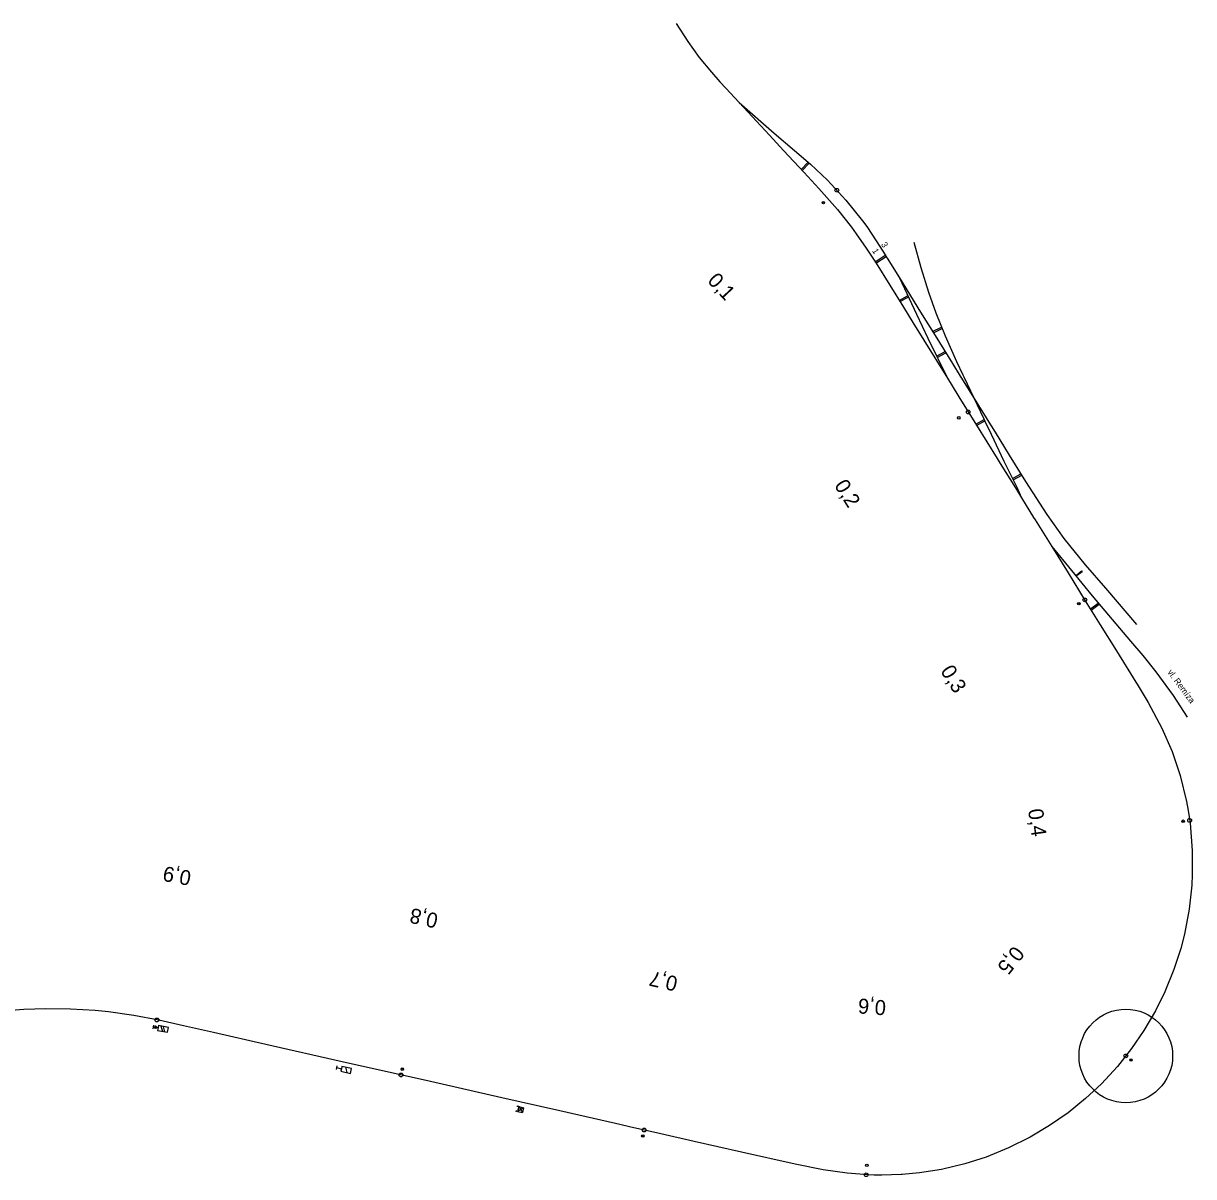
# Model space of a CAD drawing. Extents: x -738519 to -733269, y -1123734 to -1116309.
# Drawn here: x -734922.5 to -734453.9, y -1120225.8 to -1119763.8 of the extents above; entities that cross this region are included whole.
import ezdxf

# ---------------------------------------------------------------- set-up
doc = ezdxf.new("R2010")
doc.units = 0
doc.layers.add('Vrstva 1', color=7, linetype='Continuous')
doc.layers.add('Vrstva 7', color=7, linetype='Continuous')

msp = doc.modelspace()

# ---------------------------------------------------------------- linework, layer by layer
at = {"layer": 'Vrstva 1'}
for p, q in [((-734564.81, -1119880.31), (-734560.35, -1119889.86)), ((-734564.81, -1119880.31), (-734560.35, -1119889.86)), ((-734560.35, -1119889.86), (-734552.51, -1119905.98)), ((-734560.35, -1119889.86), (-734552.51, -1119905.98)), ((-734561.94, -1119890.77), (-734552.51, -1119905.98)), ((-734561.94, -1119890.77), (-734552.51, -1119905.98)), ((-734534.97, -1119928.42), (-734529.82, -1119939.22)), ((-734534.97, -1119928.42), (-734529.82, -1119939.22))]:
    msp.add_line(p, q, dxfattribs=at)
for points in [[(-734661.15, -1119763.83), (-734656.4, -1119771.12), (-734651.88, -1119777.47), (-734646.99, -1119783.39), (-734643.65, -1119787.17)], [(-734661.15, -1119763.83), (-734656.4, -1119771.12), (-734651.88, -1119777.47), (-734646.99, -1119783.39), (-734643.65, -1119787.17)], [(-734643.65, -1119787.17), (-734641.23, -1119789.79), (-734635.88, -1119795.55), (-734623.72, -1119808.66)], [(-734643.65, -1119787.17), (-734641.23, -1119789.79), (-734635.88, -1119795.55), (-734621.84, -1119807.82)], [(-734643.65, -1119787.17), (-734641.23, -1119789.79), (-734635.88, -1119795.55), (-734623.72, -1119808.66)], [(-734643.65, -1119787.17), (-734641.23, -1119789.79), (-734635.88, -1119795.55), (-734621.84, -1119807.82)], [(-734623.72, -1119808.66), (-734618.07, -1119814.79), (-734609.83, -1119823.62), (-734603.94, -1119829.94), (-734596.49, -1119838.41), (-734590.93, -1119845.44), (-734588.98, -1119848.11), (-734585, -1119853.83), (-734581.07, -1119859.88), (-734575.59, -1119868.67), (-734570.12, -1119877.53), (-734566.34, -1119883.67), (-734561.94, -1119890.77)], [(-734623.72, -1119808.66), (-734618.07, -1119814.79), (-734609.83, -1119823.62), (-734603.94, -1119829.94), (-734596.49, -1119838.41), (-734590.93, -1119845.44), (-734588.98, -1119848.11), (-734585, -1119853.83), (-734581.07, -1119859.88), (-734575.59, -1119868.67), (-734570.12, -1119877.53), (-734566.34, -1119883.67), (-734561.94, -1119890.77)], [(-734621.84, -1119807.82), (-734613.76, -1119814.7), (-734607.32, -1119820.27), (-734600.52, -1119826.61), (-734593.11, -1119834.58), (-734586.45, -1119842.91), (-734584.75, -1119845.25), (-734581.04, -1119850.86), (-734577.18, -1119856.99)], [(-734621.84, -1119807.82), (-734613.76, -1119814.7), (-734607.32, -1119820.27), (-734600.52, -1119826.61), (-734593.11, -1119834.58), (-734586.45, -1119842.91), (-734584.75, -1119845.25), (-734581.04, -1119850.86), (-734577.18, -1119856.99)], [(-734565.97, -1119851.41), (-734563.19, -1119861.58), (-734560.11, -1119871.47), (-734557.15, -1119879.72), (-734553.44, -1119889.01), (-734548.82, -1119899.31)], [(-734565.97, -1119851.41), (-734563.19, -1119861.58), (-734560.11, -1119871.47), (-734557.15, -1119879.72), (-734553.44, -1119889.01), (-734548.82, -1119899.31)], [(-734577.18, -1119856.99), (-734576.62, -1119857.91), (-734571.73, -1119865.79), (-734563.24, -1119879.48)], [(-734577.18, -1119856.99), (-734576.62, -1119857.91), (-734571.73, -1119865.79), (-734564.81, -1119880.31)], [(-734577.18, -1119856.99), (-734576.62, -1119857.91), (-734571.73, -1119865.79), (-734563.24, -1119879.48)], [(-734577.18, -1119856.99), (-734576.62, -1119857.91), (-734571.73, -1119865.79), (-734564.81, -1119880.31)], [(-734563.24, -1119879.48), (-734557.4, -1119888.87), (-734550.43, -1119900.11)], [(-734563.24, -1119879.48), (-734557.4, -1119888.87), (-734550.43, -1119900.11)], [(-734550.43, -1119900.11), (-734547.31, -1119905.14), (-734546.82, -1119905.94), (-734536.98, -1119921.77), (-734536.51, -1119922.56), (-734533.4, -1119927.58)], [(-734550.43, -1119900.11), (-734547.31, -1119905.14), (-734546.82, -1119905.94), (-734536.98, -1119921.77), (-734536.51, -1119922.56), (-734533.4, -1119927.58)], [(-734548.82, -1119899.31), (-734546.31, -1119904.61), (-734545.9, -1119905.46), (-734537.89, -1119922.29), (-734537.48, -1119923.12), (-734534.97, -1119928.42)], [(-734548.82, -1119899.31), (-734546.31, -1119904.61), (-734545.9, -1119905.46), (-734537.89, -1119922.29), (-734537.48, -1119923.12), (-734534.97, -1119928.42)], [(-734552.51, -1119905.98), (-734548.35, -1119912.69), (-734547.91, -1119913.38)], [(-734552.51, -1119905.98), (-734548.35, -1119912.69), (-734547.91, -1119913.38)], [(-734547.91, -1119913.38), (-734540.83, -1119924.83), (-734532.61, -1119938.09), (-734531.36, -1119940.09)], [(-734547.91, -1119913.38), (-734540.83, -1119924.83), (-734532.61, -1119938.09), (-734531.36, -1119940.09)], [(-734533.4, -1119927.58), (-734527.75, -1119936.72), (-734521.2, -1119947.31), (-734512.7, -1119960.57), (-734505.79, -1119970.12), (-734497.3, -1119980.65), (-734489.15, -1119990.09), (-734476.71, -1120004.56)], [(-734533.4, -1119927.58), (-734527.75, -1119936.72), (-734521.2, -1119947.31), (-734512.7, -1119960.57), (-734505.79, -1119970.12), (-734497.3, -1119980.65), (-734489.15, -1119990.09), (-734476.71, -1120004.56)], [(-734531.36, -1119940.09), (-734525.27, -1119949.91), (-734522.85, -1119953.82), (-734517.96, -1119961.71), (-734517.34, -1119962.72)], [(-734531.36, -1119940.09), (-734525.27, -1119949.91), (-734522.85, -1119953.82), (-734517.96, -1119961.71), (-734517.34, -1119962.72)], [(-734529.82, -1119939.22), (-734524.74, -1119949.62), (-734522.85, -1119953.82), (-734517.96, -1119961.71), (-734517.34, -1119962.72)], [(-734529.82, -1119939.22), (-734524.74, -1119949.62), (-734522.85, -1119953.82), (-734517.96, -1119961.71), (-734517.34, -1119962.72)], [(-734517.34, -1119962.72), (-734516.7, -1119963.74), (-734510.69, -1119973.42), (-734504.18, -1119983.89)], [(-734517.34, -1119962.72), (-734516.7, -1119963.74), (-734510.69, -1119973.42), (-734502.85, -1119982.93)], [(-734517.34, -1119962.72), (-734516.7, -1119963.74), (-734510.69, -1119973.42), (-734504.18, -1119983.89)], [(-734517.34, -1119962.72), (-734516.7, -1119963.74), (-734510.69, -1119973.42), (-734502.85, -1119982.93)], [(-734504.18, -1119983.89), (-734497.25, -1119995.08), (-734491.25, -1120004.74), (-734484.76, -1120015.19), (-734480.86, -1120021.45), (-734480.18, -1120022.55), (-734476.99, -1120027.68), (-734476.46, -1120028.54), (-734472.03, -1120035.88), (-734466.54, -1120046.18), (-734462.52, -1120055.45), (-734459.28, -1120065.13), (-734456.73, -1120075.49), (-734456.03, -1120079.17), (-734455.32, -1120084.21), (-734454.4, -1120095.11), (-734454.44, -1120105.99), (-734454.54, -1120107.84), (-734454.6, -1120109.09), (-734455.62, -1120118.65), (-734457.52, -1120128.68), (-734458.98, -1120134.34), (-734461.74, -1120142.87), (-734465.37, -1120151.8), (-734469.15, -1120159.42), (-734473.78, -1120167.32), (-734478.71, -1120174.52), (-734484.35, -1120181.61), (-734490.79, -1120188.56), (-734497.21, -1120194.54), (-734504.15, -1120200.17), (-734511.58, -1120205.34), (-734519.33, -1120209.98), (-734527.98, -1120214.28), (-734537.01, -1120217.94), (-734545.52, -1120220.65), (-734554.88, -1120222.87), (-734563.63, -1120224.26), (-734570.58, -1120224.9), (-734571.05, -1120224.92), (-734578.72, -1120225.21), (-734581.85, -1120225.14), (-734584.23, -1120225.09), (-734592.62, -1120224.46), (-734602.24, -1120223.05), (-734613.42, -1120220.79)], [(-734504.18, -1119983.89), (-734497.25, -1119995.08), (-734491.25, -1120004.74), (-734484.76, -1120015.19), (-734480.86, -1120021.45), (-734480.18, -1120022.55), (-734476.99, -1120027.68), (-734476.46, -1120028.54), (-734472.03, -1120035.88), (-734466.54, -1120046.18), (-734462.52, -1120055.45), (-734459.28, -1120065.13), (-734456.73, -1120075.49), (-734456.03, -1120079.17), (-734455.32, -1120084.21), (-734454.4, -1120095.11), (-734454.44, -1120105.99), (-734454.54, -1120107.84), (-734454.6, -1120109.09), (-734455.62, -1120118.65), (-734457.52, -1120128.68), (-734458.98, -1120134.34), (-734461.74, -1120142.87), (-734465.37, -1120151.8), (-734469.15, -1120159.42), (-734473.78, -1120167.32), (-734478.71, -1120174.52), (-734484.35, -1120181.61), (-734490.79, -1120188.56), (-734497.21, -1120194.54), (-734504.15, -1120200.17), (-734511.58, -1120205.34), (-734519.33, -1120209.98), (-734527.98, -1120214.28), (-734537.01, -1120217.94), (-734545.52, -1120220.65), (-734554.88, -1120222.87), (-734563.63, -1120224.26), (-734570.58, -1120224.9), (-734571.05, -1120224.92), (-734578.72, -1120225.21), (-734581.85, -1120225.14), (-734584.23, -1120225.09), (-734592.62, -1120224.46), (-734602.24, -1120223.05), (-734613.42, -1120220.79)], [(-734502.85, -1119982.93), (-734494.46, -1119993.2), (-734489.38, -1119999.18), (-734479.09, -1120011.24), (-734474.27, -1120017.09), (-734469.03, -1120023.64), (-734462.03, -1120033.09), (-734456.42, -1120041.8)], [(-734502.85, -1119982.93), (-734494.46, -1119993.2), (-734489.38, -1119999.18), (-734479.09, -1120011.24), (-734474.27, -1120017.09), (-734469.03, -1120023.64), (-734462.03, -1120033.09), (-734456.42, -1120041.8)], [(-734858.48, -1120165.34), (-734868.3, -1120163.18), (-734878.26, -1120161.29), (-734888.48, -1120159.82), (-734893.81, -1120159.29), (-734903.72, -1120158.67), (-734913.62, -1120158.56), (-734922.39, -1120158.89), (-734927.49, -1120159.26), (-734938.14, -1120160.47), (-734948.63, -1120162.22), (-734955.93, -1120163.8), (-734961.26, -1120165.13), (-734970.23, -1120167.73), (-734979.17, -1120170.78), (-734984.57, -1120172.85), (-734992.91, -1120176.44), (-734998.02, -1120178.89), (-735005.2, -1120182.65), (-735013.61, -1120187.35), (-735022.2, -1120192.38), (-735037.65, -1120201.44), (-735048.63, -1120207.9)], [(-734858.48, -1120165.34), (-734868.3, -1120163.18), (-734878.26, -1120161.29), (-734888.48, -1120159.82), (-734893.81, -1120159.29), (-734903.72, -1120158.67), (-734913.62, -1120158.56), (-734922.39, -1120158.89), (-734927.49, -1120159.26), (-734938.14, -1120160.47), (-734948.63, -1120162.22), (-734955.93, -1120163.8), (-734961.26, -1120165.13), (-734970.23, -1120167.73), (-734979.17, -1120170.78), (-734984.57, -1120172.85), (-734992.91, -1120176.44), (-734998.02, -1120178.89), (-735005.2, -1120182.65), (-735013.61, -1120187.35), (-735022.2, -1120192.38), (-735037.65, -1120201.44), (-735048.63, -1120207.9)], [(-734613.42, -1120220.79), (-734634.89, -1120215.96), (-734653.9, -1120211.66), (-734667.21, -1120208.65), (-734679.78, -1120205.8), (-734683.65, -1120204.92), (-734685.4, -1120204.52), (-734700.12, -1120201.2), (-734707.73, -1120199.48), (-734730.99, -1120194.2), (-734759.47, -1120187.75), (-734794.9, -1120179.75), (-734825.42, -1120172.84), (-734846.47, -1120168.09), (-734858.48, -1120165.34)], [(-734613.42, -1120220.79), (-734634.89, -1120215.96), (-734653.9, -1120211.66), (-734667.21, -1120208.65), (-734679.78, -1120205.8), (-734683.65, -1120204.92), (-734685.4, -1120204.52), (-734700.12, -1120201.2), (-734707.73, -1120199.48), (-734730.99, -1120194.2), (-734759.47, -1120187.75), (-734794.9, -1120179.75), (-734825.42, -1120172.84), (-734846.47, -1120168.09), (-734858.48, -1120165.34)]]:
    msp.add_lwpolyline(points, dxfattribs=at)
at = {"layer": 'Vrstva 7'}
for p, q in [((-734611.07, -1119822.29), (-734608.3, -1119819.42)), ((-734611.07, -1119822.29), (-734608.3, -1119819.42)), ((-734610.66, -1119822.73), (-734607.85, -1119819.81)), ((-734610.66, -1119822.73), (-734607.85, -1119819.81)), ((-734602.18, -1119835.62), (-734602.11, -1119835.7)), ((-734602.18, -1119835.62), (-734602.11, -1119835.7)), ((-734581.42, -1119859.33), (-734577.35, -1119856.73)), ((-734581.42, -1119859.33), (-734577.35, -1119856.73)), ((-734581.09, -1119859.84), (-734577.03, -1119857.24)), ((-734581.09, -1119859.84), (-734577.03, -1119857.24)), ((-734571.82, -1119874.78), (-734568.43, -1119872.91)), ((-734571.82, -1119874.78), (-734568.43, -1119872.91)), ((-734571.5, -1119875.29), (-734568.17, -1119873.45)), ((-734571.5, -1119875.29), (-734568.17, -1119873.45)), ((-734558.41, -1119887.26), (-734554.85, -1119885.47)), ((-734558.41, -1119887.26), (-734554.85, -1119885.47)), ((-734558.09, -1119887.77), (-734554.63, -1119886.03)), ((-734558.09, -1119887.77), (-734554.63, -1119886.03)), ((-734556.82, -1119897.12), (-734553.44, -1119895.25)), ((-734556.82, -1119897.12), (-734553.44, -1119895.25)), ((-734556.56, -1119897.66), (-734553.12, -1119895.76)), ((-734556.56, -1119897.66), (-734553.12, -1119895.76)), ((-734547.95, -1119921.8), (-734547.9, -1119921.88)), ((-734547.95, -1119921.8), (-734547.9, -1119921.88)), ((-734541.14, -1119924.33), (-734537.79, -1119922.49)), ((-734541.14, -1119924.33), (-734537.79, -1119922.49)), ((-734540.82, -1119924.84), (-734537.53, -1119923.03)), ((-734540.82, -1119924.84), (-734537.53, -1119923.03)), ((-734526.43, -1119946.16), (-734523.06, -1119944.3)), ((-734526.43, -1119946.16), (-734523.06, -1119944.3)), ((-734526.17, -1119946.7), (-734522.74, -1119944.81)), ((-734526.17, -1119946.7), (-734522.74, -1119944.81)), ((-734500.71, -1119984.73), (-734498.52, -1119983.46)), ((-734500.71, -1119984.73), (-734498.52, -1119983.46)), ((-734499.87, -1119996.2), (-734499.8, -1119996.28)), ((-734499.87, -1119996.2), (-734499.8, -1119996.28)), ((-734495.23, -1119998.34), (-734492.06, -1119996.03)), ((-734495.23, -1119998.34), (-734492.06, -1119996.03)), ((-734494.91, -1119998.85), (-734491.67, -1119996.49)), ((-734494.91, -1119998.85), (-734491.67, -1119996.49)), ((-734458.07, -1120083.38), (-734458.05, -1120083.48)), ((-734458.07, -1120083.38), (-734458.05, -1120083.48)), ((-734870.44, -1120165.12), (-734870.72, -1120166.6)), ((-734870.44, -1120165.12), (-734870.72, -1120166.6)), ((-734869.56, -1120165.95), (-734869.65, -1120165.93)), ((-734869.56, -1120165.95), (-734869.65, -1120165.93)), ((-734867.45, -1120165.44), (-734866.84, -1120167.59)), ((-734867.45, -1120165.44), (-734866.84, -1120167.59)), ((-734865.86, -1120167.78), (-734866.47, -1120165.63)), ((-734865.86, -1120167.78), (-734866.47, -1120165.63)), ((-734478.94, -1120179.03), (-734479.01, -1120179.11)), ((-734478.94, -1120179.03), (-734479.01, -1120179.11)), ((-734796.98, -1120181.41), (-734797.31, -1120182.87)), ((-734796.98, -1120181.41), (-734797.31, -1120182.87)), ((-734793.51, -1120181.94), (-734792.98, -1120184.11)), ((-734793.51, -1120181.94), (-734792.98, -1120184.11)), ((-734770.75, -1120182.76), (-734770.85, -1120182.74)), ((-734770.75, -1120182.76), (-734770.85, -1120182.74)), ((-734725.18, -1120199.8), (-734725.07, -1120199.32)), ((-734725.18, -1120199.8), (-734725.07, -1120199.32)), ((-734724.64, -1120199.68), (-734725.13, -1120199.56)), ((-734724.64, -1120199.68), (-734725.13, -1120199.56)), ((-734724.72, -1120197.86), (-734724.6, -1120197.37)), ((-734724.72, -1120197.86), (-734724.6, -1120197.37)), ((-734724.18, -1120197.73), (-734724.66, -1120197.61)), ((-734724.18, -1120197.73), (-734724.66, -1120197.61)), ((-734724.18, -1120197.73), (-734724.64, -1120199.68)), ((-734724.18, -1120197.73), (-734724.64, -1120199.68)), ((-734722.23, -1120198.19), (-734724.64, -1120199.68)), ((-734722.23, -1120198.19), (-734724.64, -1120199.68)), ((-734724.64, -1120199.68), (-734722.69, -1120200.14)), ((-734724.64, -1120199.68), (-734722.69, -1120200.14)), ((-734724.18, -1120197.73), (-734722.23, -1120198.19)), ((-734724.18, -1120197.73), (-734722.69, -1120200.14)), ((-734724.18, -1120197.73), (-734722.23, -1120198.19)), ((-734724.18, -1120197.73), (-734722.69, -1120200.14)), ((-734722.23, -1120198.19), (-734722.69, -1120200.14)), ((-734722.23, -1120198.19), (-734722.69, -1120200.14)), ((-734674.43, -1120209.52), (-734674.53, -1120209.5)), ((-734674.43, -1120209.52), (-734674.53, -1120209.5)), ((-734584.71, -1120221.28), (-734584.81, -1120221.28)), ((-734584.71, -1120221.28), (-734584.81, -1120221.28))]:
    msp.add_line(p, q, dxfattribs=at)
for points in [[(-734498.77, -1119983.15), (-734500.45, -1119985.04), (-734500.71, -1119984.73), (-734498.77, -1119983.15), (-734498.52, -1119983.46), (-734500.45, -1119985.04)], [(-734498.77, -1119983.15), (-734500.45, -1119985.04), (-734500.71, -1119984.73), (-734498.77, -1119983.15), (-734498.52, -1119983.46), (-734500.45, -1119985.04)], [(-734870.58, -1120165.86), (-734868.62, -1120166.24), (-734868.8, -1120167.22), (-734864.87, -1120167.97), (-734864.5, -1120166), (-734868.43, -1120165.25), (-734868.62, -1120166.24)], [(-734870.58, -1120165.86), (-734868.62, -1120166.24), (-734868.8, -1120167.22), (-734864.87, -1120167.97), (-734864.5, -1120166), (-734868.43, -1120165.25), (-734868.62, -1120166.24)], [(-734797.15, -1120182.14), (-734795.2, -1120182.58), (-734795.42, -1120183.56), (-734791.52, -1120184.44), (-734791.08, -1120182.49), (-734794.98, -1120181.61), (-734795.2, -1120182.58)], [(-734797.15, -1120182.14), (-734795.2, -1120182.58), (-734795.42, -1120183.56), (-734791.52, -1120184.44), (-734791.08, -1120182.49), (-734794.98, -1120181.61), (-734795.2, -1120182.58)]]:
    msp.add_lwpolyline(points, dxfattribs=at)
for centre, radius in [((-734596.76, -1119830.65), 0.75), ((-734596.76, -1119830.65), 0.75), ((-734602.15, -1119835.66), 0.5), ((-734602.15, -1119835.66), 0.5), ((-734544.13, -1119919.49), 0.75), ((-734544.13, -1119919.49), 0.75), ((-734547.93, -1119921.84), 0.5), ((-734547.93, -1119921.84), 0.5), ((-734499.84, -1119996.24), 0.5), ((-734499.84, -1119996.24), 0.5), ((-734497.45, -1119994.76), 0.75), ((-734497.45, -1119994.76), 0.75), ((-734455.48, -1120083.07), 0.75), ((-734455.48, -1120083.07), 0.75), ((-734458.06, -1120083.43), 0.5), ((-734458.06, -1120083.43), 0.5), ((-734869.05, -1120163.04), 0.75), ((-734869.05, -1120163.04), 0.75), ((-734481.03, -1120177.43), 18.75), ((-734869.6, -1120165.94), 0.5), ((-734869.6, -1120165.94), 0.5), ((-734481.03, -1120177.43), 0.75), ((-734478.98, -1120179.07), 0.5), ((-734478.98, -1120179.07), 0.5), ((-734771.32, -1120185.07), 0.75), ((-734771.32, -1120185.07), 0.75), ((-734770.8, -1120182.75), 0.5), ((-734770.8, -1120182.75), 0.5), ((-734674.48, -1120209.51), 0.5), ((-734674.48, -1120209.51), 0.5), ((-734673.94, -1120207.12), 0.75), ((-734673.94, -1120207.12), 0.75), ((-734584.76, -1120221.28), 0.5), ((-734584.76, -1120221.28), 0.5), ((-734585.04, -1120225.03), 0.75), ((-734585.04, -1120225.03), 0.75)]:
    msp.add_circle(centre, radius, dxfattribs=at)

# ---------------------------------------------------------------- texts
at = {"layer": 'Vrstva 1'}
for s, rotation, p in [('3', 302.1663, (-734579.17, -1119852.36)), ('3', 302.1663, (-734579.17, -1119852.36)), ('1', 301.9274, (-734582.73, -1119854.91)), ('1', 301.9274, (-734582.73, -1119854.91)), ('vl. Remíza', 306.5318, (-734464.5, -1120023.79)), ('vl. Remíza', 306.5318, (-734464.5, -1120023.79))]:
    msp.add_text(s, height=2.5, rotation=rotation, dxfattribs=at).set_placement(p)
at = {"layer": 'Vrstva 7'}
for s, rotation, p in [('0,1', 312.9178, (-734648.91, -1119867.14)), ('0,1', 312.9178, (-734648.91, -1119867.14)), ('0,2', 301.7502, (-734597.98, -1119948.86)), ('0,2', 301.7502, (-734597.98, -1119948.86)), ('0,3', 301.8479, (-734555.46, -1120023.21)), ('0,3', 301.8479, (-734555.46, -1120023.21)), ('0,4', 278.0059, (-734520.2, -1120078.82)), ('0,4', 278.0059, (-734520.2, -1120078.82)), ('0,9', 169.221, (-734854.99, -1120103.43)), ('0,9', 169.221, (-734854.99, -1120103.43)), ('0,8', 167.2679, (-734756.09, -1120120.57)), ('0,8', 167.2679, (-734756.09, -1120120.57)), ('0,5', 231.4794, (-734525.88, -1120132.95)), ('0,7', 167.2383, (-734660.13, -1120145.82)), ('0,7', 167.2383, (-734660.13, -1120145.82)), ('0,6', 175.6645, (-734576.88, -1120155.22)), ('0,6', 175.6645, (-734576.88, -1120155.22))]:
    msp.add_text(s, height=6, rotation=rotation, dxfattribs=at).set_placement(p)

doc.saveas('drawing.dxf')
